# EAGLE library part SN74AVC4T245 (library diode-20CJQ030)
Ti's SN74AVC4T245 4-bit dual supply bus transceiver with configurable voltage transsaltion and 3-state outputs Description: This 4-bit noninverting bus transceiver uses two separate configurable power-supply rails. The A port is designed to track VCCA. VCCA accepts any supply voltage from 1.2 V to 3.6 V. The B port is designed to track VCCB. VCCB accepts any supply voltage from 1.2 V to 3.6 V. The SN74AVC4T245 is optimized to operate with VCCA/VCCB set at 1.4 V to 3.6 V. It is operational with VCCA/VCCB as low as 1.2 V. This allows for universal low-voltage bidirectional translation between any of the 1.2-V, 1.5-V, 1.8-V, 2.5-V, and 3.3-V voltage nodes. The SN74AVC4T245 is designed for asynchronous communication between data buses. The device transmits data from the A bus to the B bus or from the B bus to the A bus, depending on the logic level at the direction-control (DIR) input. The output-enable (#OE) input can be used to disable the outputs so the buses are effectively isolated. The SN74AVC4T245 is designed so that the control pins (1DIR, 2DIR, #1OE, and #2OE) are supplied by VCCA. This device is fully specified for partial-power-down applications using Ioff. The Ioff circuitry disables the outputs, preventing damaging current backflow through the device when it is powered down. Features: Control Inputs VIH/VIL Levels are Referenced to VCCA Voltage Fully Configurable Dual-Rail Design Allows Each Port to Operate Over the Full 1.2-V to 3.6-V Power-Supply Range I/Os Are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
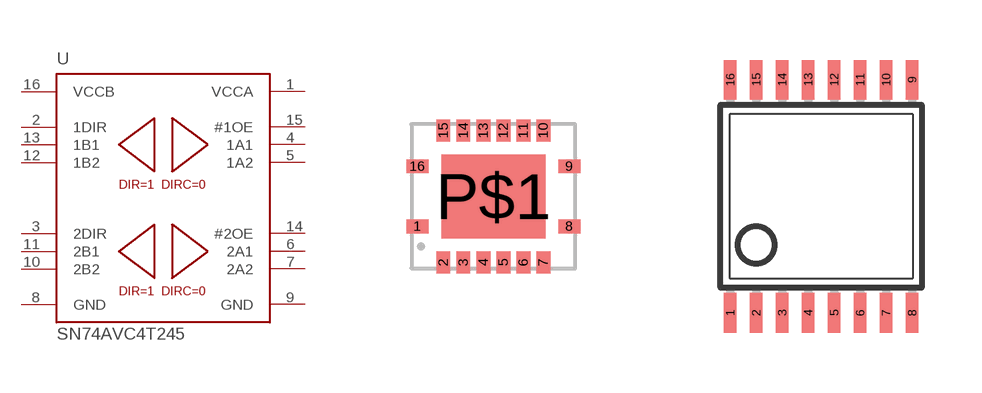
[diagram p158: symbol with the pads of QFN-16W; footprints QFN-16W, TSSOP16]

Designator prefix U

## SN74AVC4T245RGY  [QFN-16W]
1  VCCA  pwr
2  1DIR  in
3  2DIR  in
4  1A1
5  1A2
6  2A1
7  2A2
8  GND  pwr
9  GND  pwr
10  2B2
11  2B1
12  1B2
13  1B1
14  #2OE  in
15  #1OE  in
16  VCCB  pwr

## SN74AVC4T245PW  [TSSOP16]
Pads as for QFN-16W

## SN74AVC4T245DGV  [TVSOP16]
Pads as for QFN-16W

## Footprint QFN-16W (pad centres in mm)
smd 0.55 x 0.35: 1 -1.9,-0.75; 8 1.9,-0.75; 9 1.9,0.75; 16 -1.9,0.75
smd 0.35 x 0.55: 2 -1.25,-1.65; 3 -0.75,-1.65; 4 -0.25,-1.65; 5 0.25,-1.65; 6 0.75,-1.65; 7 1.25,-1.65; 10 1.25,1.65; 11 0.75,1.65; 12 0.25,1.65; 13 -0.25,1.65; 14 -0.75,1.65; 15 -1.25,1.65
smd 2.6 x 2.1: P$1 0,0

## Footprint TSSOP16 (pad centres in mm)
Thin Shrink Small Outline Plastic 16 MAX3223-MAX3243.pdf
smd 0.305 x 0.991: 1 -2.275,-2.918; 2 -1.625,-2.918; 3 -0.975,-2.918; 4 -0.325,-2.918; 5 0.325,-2.918; 6 0.975,-2.918; 7 1.625,-2.918; 8 2.275,-2.918; 9 2.275,2.918; 10 1.625,2.918; 11 0.975,2.918; 12 0.325,2.918; 13 -0.325,2.918; 14 -0.975,2.918; 15 -1.625,2.918; 16 -2.275,2.918

## Footprint TVSOP16 (pad centres in mm)
Plastic Small Outline
smd 0.28 x 1: 1 -1.4,-3.1; 2 -1,-3.1; 3 -0.6,-3.1; 4 -0.2,-3.1; 5 0.2,-3.1; 6 0.6,-3.1; 7 1,-3.1; 8 1.4,-3.1; 9 1.4,3.1; 10 1,3.1; 11 0.6,3.1; 12 0.2,3.1; 13 -0.2,3.1; 14 -0.6,3.1; 15 -1,3.1; 16 -1.4,3.1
